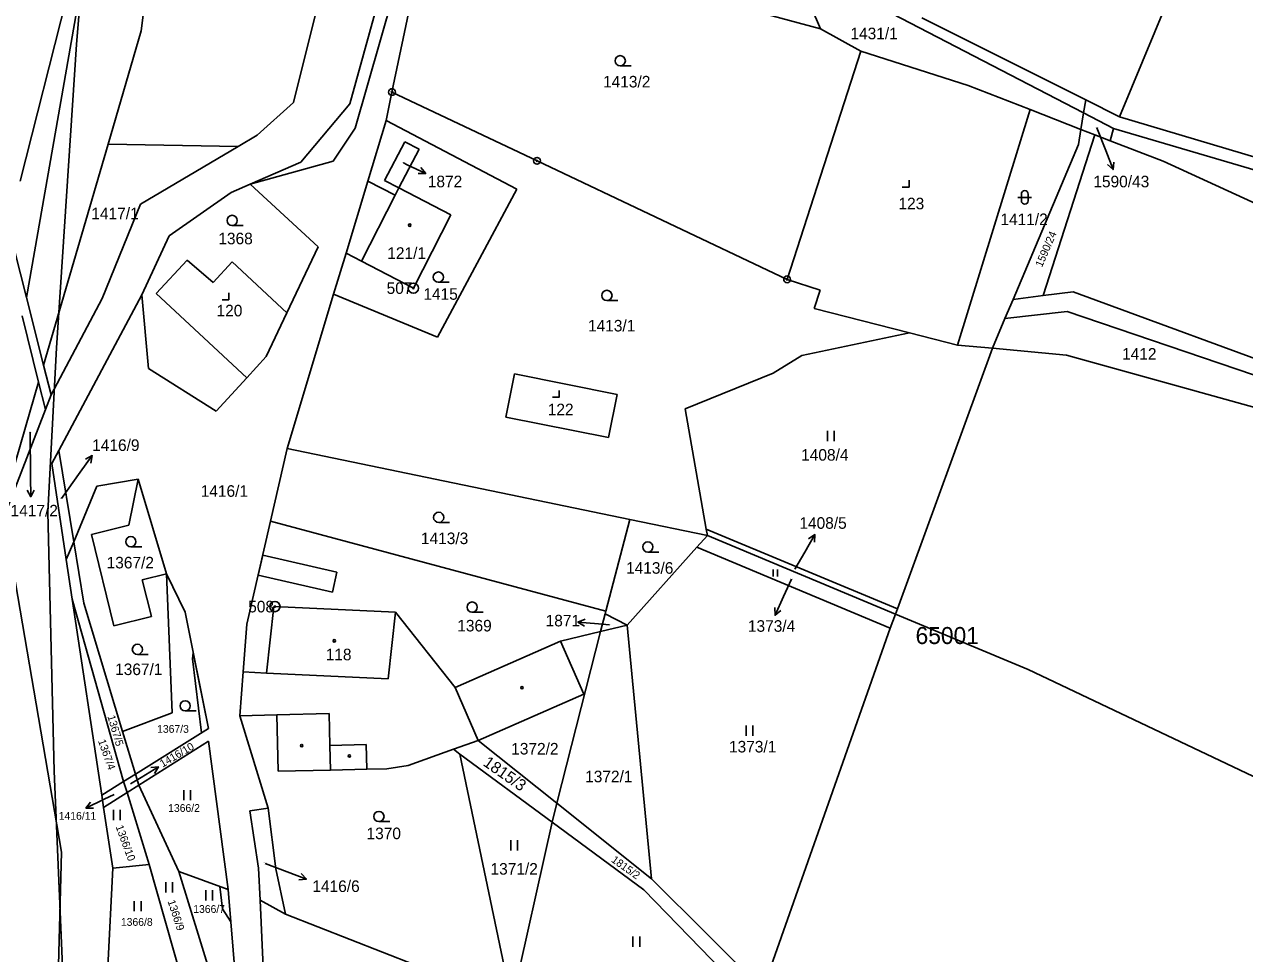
# Model space of a CAD drawing. Extents: x -546762 to -540209, y -1046851 to -1035694.
# Drawn here: x -543585.9 to -543406.7, y -1041154.9 to -1041018.4 of the extents above; entities that cross this region are included whole.
import ezdxf

# ---------------------------------------------------------------- set-up
doc = ezdxf.new("R2010")
doc.units = 0
for name, color, linetype in [('Vrstva 1', 7, 'Continuous'), ('Vrstva 16', 7, 'Continuous'), ('Vrstva 17', 7, 'Continuous'), ('Vrstva 18', 7, 'Continuous'), ('Vrstva 19', 7, 'Continuous'), ('Vrstva 24', 7, 'Continuous'), ('Vrstva 25', 7, 'Continuous'), ('Vrstva 3', 7, 'Continuous'), ('Vrstva 30', 7, 'Continuous'), ('Vrstva 37', 7, 'Continuous'), ('Vrstva 4', 7, 'Continuous'), ('Vrstva 52', 7, 'Continuous'), ('Vrstva 53', 7, 'Continuous'), ('Vrstva 6', 7, 'Continuous')]:
    doc.layers.add(name, color=color, linetype=linetype)

msp = doc.modelspace()

# ---------------------------------------------------------------- linework, layer by layer
at = {"layer": 'Vrstva 1'}
for p, q in [((-543564.16, -1040935.84), (-543585.58, -1041058.49)), ((-543540.21, -1041005.09), (-543546.36, -1041029.86)), ((-543531.75, -1041014.27), (-543537.3, -1041033.62)), ((-543537.3, -1041033.62), (-543540.52, -1041038.48)), ((-543540.52, -1041038.48), (-543552.73, -1041041.85))]:
    msp.add_line(p, q, dxfattribs=at)
for points in [[(-543564.64, -1040987.05), (-543568.73, -1041019.34)], [(-543531.89, -1041028.33), (-543526.68, -1041003.47)], [(-543526.68, -1041003.47), (-543468.97, -1041019.03)], [(-543538.08, -1041030.04), (-543531.44, -1041005.97)], [(-543468.97, -1041019.03), (-543473.2, -1041009.11)], [(-543473.2, -1041009.11), (-543430.31, -1041031.4)], [(-543579.71, -1041014.54), (-543586.53, -1041041.43)], [(-543454.04, -1041017.4), (-543429.99, -1041029.48)], [(-543573.59, -1041036), (-543568.73, -1041019.34)], [(-543468.97, -1041019.03), (-543463.04, -1041022.33)], [(-543463.04, -1041022.33), (-543473.85, -1041055.84)], [(-543463.04, -1041022.33), (-543447.28, -1041027.35)], [(-543447.28, -1041027.35), (-543438.15, -1041030.91)], [(-543531.89, -1041028.33), (-543532.76, -1041032.5)], [(-543510.59, -1041038.43), (-543531.89, -1041028.33)], [(-543551.68, -1041034.65), (-543546.36, -1041029.86)], [(-543538.08, -1041030.04), (-543545.26, -1041038.61)], [(-543438.15, -1041030.91), (-543448.82, -1041065.5)], [(-543438.15, -1041030.91), (-543430.7, -1041033.81)], [(-543430.31, -1041031.4), (-543429.99, -1041029.48)], [(-543532.76, -1041032.5), (-543535.45, -1041041.41)], [(-543532.76, -1041032.5), (-543513.53, -1041042.59)], [(-543430.7, -1041033.81), (-543430.31, -1041031.4)], [(-543551.68, -1041034.65), (-543554.51, -1041036.33)], [(-543431.06, -1041036.04), (-543430.7, -1041033.81)], [(-543583.06, -1041068.45), (-543573.59, -1041036)], [(-543573.59, -1041036), (-543554.51, -1041036.33)], [(-543568.85, -1041044.82), (-543554.51, -1041036.33)], [(-543532.97, -1041041.3), (-543530.02, -1041035.62)], [(-543530.02, -1041035.62), (-543527.92, -1041036.72)], [(-543431.06, -1041036.04), (-543440.65, -1041058.78)], [(-543527.92, -1041036.72), (-543530.87, -1041042.39)], [(-543545.26, -1041038.61), (-543552.73, -1041041.85)], [(-543473.85, -1041055.84), (-543510.59, -1041038.43)], [(-543552.73, -1041041.85), (-543555.51, -1041043.06)], [(-543542.75, -1041051.04), (-543552.73, -1041041.85)], [(-543535.45, -1041041.41), (-543538.64, -1041051.98)], [(-543531.43, -1041043.49), (-543535.45, -1041041.41)], [(-543530.87, -1041042.39), (-543532.97, -1041041.3)], [(-543555.51, -1041043.06), (-543564.64, -1041049.44)], [(-543531.43, -1041043.49), (-543530.87, -1041042.39)], [(-543530.87, -1041042.39), (-543523.24, -1041046.36)], [(-543513.53, -1041042.59), (-543525.21, -1041064.33)], [(-543574.46, -1041058.66), (-543568.85, -1041044.82)], [(-543523.24, -1041046.36), (-543528.75, -1041057.13)], [(-543588.22, -1041048.06), (-543585.58, -1041058.49)], [(-543564.64, -1041049.44), (-543568.66, -1041058.14)], [(-543542.75, -1041051.04), (-543547.34, -1041060.78)], [(-543538.64, -1041051.98), (-543540.46, -1041058.03)], [(-543536.38, -1041053.16), (-543538.64, -1041051.98)], [(-543561.96, -1041053), (-543566.53, -1041057.9)], [(-543558.18, -1041056.28), (-543561.96, -1041053)], [(-543555.39, -1041053.28), (-543558.18, -1041056.28)], [(-543555.39, -1041053.28), (-543547.34, -1041060.78)], [(-543528.75, -1041057.13), (-543536.38, -1041053.16)], [(-543469, -1041057.41), (-543473.85, -1041055.84)], [(-543566.53, -1041057.9), (-543553.23, -1041070.32)], [(-543540.46, -1041058.03), (-543547.28, -1041080.67)], [(-543540.46, -1041058.03), (-543525.21, -1041064.33)], [(-543469, -1041057.41), (-543469.87, -1041060.12)], [(-543585.58, -1041058.49), (-543583.06, -1041068.45)], [(-543581.96, -1041072.79), (-543574.46, -1041058.66)], [(-543568.66, -1041058.14), (-543580.83, -1041080.99)], [(-543567.67, -1041068.94), (-543568.66, -1041058.14)], [(-543440.65, -1041058.78), (-543441.85, -1041061.61)], [(-543586.19, -1041061.19), (-543583.79, -1041070.95)], [(-543547.34, -1041060.78), (-543550.36, -1041067.18)], [(-543469.87, -1041060.12), (-543455.88, -1041063.7)], [(-543441.85, -1041061.61), (-543443.69, -1041065.97)], [(-543471.67, -1041067.04), (-543455.88, -1041063.7)], [(-543455.88, -1041063.7), (-543448.82, -1041065.5)], [(-543471.67, -1041067.04), (-543475.88, -1041069.64)], [(-543443.69, -1041065.97), (-543457.66, -1041104.26)], [(-543448.82, -1041065.5), (-543443.69, -1041065.97)], [(-543583.06, -1041068.45), (-543581.96, -1041072.79)], [(-543550.36, -1041067.18), (-543553.23, -1041070.32)], [(-543567.67, -1041068.94), (-543557.71, -1041075.23)], [(-543553.23, -1041070.32), (-543557.71, -1041075.23)], [(-543513.9, -1041069.73), (-543515.16, -1041076.07)], [(-543498.83, -1041072.74), (-543513.9, -1041069.73)], [(-543475.88, -1041069.64), (-543488.85, -1041074.86)], [(-543591.7, -1041098.06), (-543583.79, -1041070.95)], [(-543583.79, -1041070.95), (-543582.8, -1041074.97)], [(-543582.8, -1041074.97), (-543581.96, -1041072.79)], [(-543498.83, -1041072.74), (-543500.1, -1041079.08)], [(-543588.85, -1041090.66), (-543582.8, -1041074.97)], [(-543485.72, -1041092.52), (-543488.85, -1041074.86)], [(-543515.16, -1041076.07), (-543500.1, -1041079.08)], [(-543580.83, -1041080.99), (-543581.85, -1041082.9)], [(-543580.83, -1041080.99), (-543578.63, -1041094.38)], [(-543547.28, -1041080.67), (-543549.73, -1041091.38)], [(-543581.85, -1041082.9), (-543579.73, -1041097.02)], [(-543578.63, -1041094.38), (-543575.23, -1041086.21)], [(-543575.23, -1041086.21), (-543569.19, -1041085.19)], [(-543569.19, -1041085.19), (-543564.99, -1041099.1)], [(-543580.46, -1041140), (-543588.85, -1041090.66)], [(-543549.73, -1041091.38), (-543553.19, -1041106.51)], [(-543500.5, -1041104.61), (-543549.73, -1041091.38)], [(-543500.5, -1041104.61), (-543496.94, -1041091.1)], [(-543485.55, -1041093.46), (-543487.11, -1041095.2)], [(-543485.55, -1041093.46), (-543485.72, -1041092.52)], [(-543485.72, -1041092.52), (-543457.66, -1041104.26)], [(-543457.94, -1041105.02), (-543485.55, -1041093.46)], [(-543579.73, -1041097.02), (-543578.63, -1041094.38)], [(-543487.11, -1041095.2), (-543497.33, -1041106.65)], [(-543458.7, -1041107.1), (-543487.11, -1041095.2)], [(-543579.73, -1041097.02), (-543578.86, -1041102.82)], [(-543562.29, -1041104.74), (-543564.99, -1041099.1)], [(-543578.86, -1041102.82), (-543574.53, -1041131.64)], [(-543549.25, -1041103.92), (-543550.34, -1041113.68)], [(-543549.25, -1041103.92), (-543531.37, -1041104.75)], [(-543500.59, -1041104.96), (-543500.5, -1041104.61)], [(-543457.66, -1041104.26), (-543457.94, -1041105.02)], [(-543562.29, -1041104.74), (-543558.83, -1041121.81)], [(-543531.37, -1041104.75), (-543522.62, -1041115.8)], [(-543501.26, -1041107.6), (-543500.59, -1041104.96)], [(-543500.59, -1041104.96), (-543497.33, -1041106.65)], [(-543457.94, -1041105.02), (-543458.7, -1041107.1)], [(-543553.19, -1041106.51), (-543553.74, -1041113.52)], [(-543507.67, -1041132.79), (-543501.26, -1041107.6)], [(-543501.26, -1041107.6), (-543507.14, -1041109.01)], [(-543497.33, -1041106.65), (-543501.26, -1041107.6)], [(-543497.33, -1041106.65), (-543493.75, -1041143.91)], [(-543477.44, -1041160.15), (-543458.7, -1041107.1)], [(-543507.14, -1041109.01), (-543522.62, -1041115.8)], [(-543507.14, -1041109.01), (-543503.73, -1041116.78)], [(-543553.74, -1041113.52), (-543554.23, -1041119.95)], [(-543553.74, -1041113.52), (-543550.34, -1041113.68)], [(-543503.73, -1041116.78), (-543519.21, -1041123.57)], [(-543554.23, -1041119.95), (-543548.82, -1041119.82)], [(-543554.23, -1041119.95), (-543550.09, -1041133.54)], [(-543548.82, -1041119.82), (-543548.63, -1041128.12)], [(-543558.83, -1041121.81), (-543569.59, -1041128.54)], [(-543558.82, -1041123.68), (-543569.1, -1041130.17)], [(-543558.82, -1041123.68), (-543555.97, -1041145.47)], [(-543522.86, -1041124.88), (-543519.21, -1041123.57)], [(-543519.21, -1041123.57), (-543507.67, -1041132.79)], [(-543529.53, -1041127.26), (-543522.86, -1041124.88)], [(-543521.91, -1041125.58), (-543522.86, -1041124.88)], [(-543508.38, -1041135.57), (-543521.91, -1041125.58)], [(-543514.28, -1041162.12), (-543521.91, -1041125.58)], [(-543548.63, -1041128.12), (-543540.93, -1041127.94)], [(-543540.93, -1041127.94), (-543535.58, -1041127.82)], [(-543535.58, -1041127.82), (-543532.65, -1041127.75)], [(-543532.65, -1041127.75), (-543529.53, -1041127.26)], [(-543571.31, -1041129.62), (-543574.53, -1041131.64)], [(-543569.59, -1041128.54), (-543571.31, -1041129.62)], [(-543571.31, -1041129.62), (-543570.81, -1041131.25)], [(-543569.59, -1041128.54), (-543569.1, -1041130.17)], [(-543570.81, -1041131.25), (-543574.26, -1041133.43)], [(-543569.1, -1041130.17), (-543570.81, -1041131.25)], [(-543574.53, -1041131.64), (-543574.26, -1041133.43)], [(-543508.38, -1041135.57), (-543507.67, -1041132.79)], [(-543507.67, -1041132.79), (-543493.75, -1041143.91)], [(-543574.26, -1041133.43), (-543572.92, -1041142.34)], [(-543552.76, -1041133.91), (-543550.09, -1041133.54)], [(-543552.76, -1041133.91), (-543551.48, -1041142.37)], [(-543550.09, -1041133.54), (-543548.96, -1041142.45)], [(-543514.28, -1041162.12), (-543508.38, -1041135.57)], [(-543494.88, -1041145.53), (-543508.38, -1041135.57)], [(-543580.46, -1041140), (-543581.72, -1041187.92)], [(-543572.92, -1041142.34), (-543573.64, -1041156.84)], [(-543551.48, -1041142.37), (-543551.27, -1041147.03)], [(-543548.96, -1041142.45), (-543547.55, -1041149.13)], [(-543493.75, -1041143.91), (-543477.44, -1041160.15)], [(-543555.97, -1041145.47), (-543554.51, -1041163.33)], [(-543494.88, -1041145.53), (-543478.32, -1041162.62)], [(-543551.27, -1041147.03), (-543549.65, -1041183.25)], [(-543551.27, -1041147.03), (-543547.55, -1041149.13)], [(-543547.55, -1041149.13), (-543514.28, -1041162.12)]]:
    msp.add_lwpolyline(points, dxfattribs=at)
at = {"layer": 'Vrstva 16'}
for p, q in [((-543427.05, -1041036.93), (-543425.96, -1041039.72)), ((-543529.65, -1041039), (-543526.94, -1041040.28)), ((-543577.68, -1041084.18), (-543575.93, -1041081.74)), ((-543584.98, -1041084.79), (-543584.95, -1041087.79)), ((-543471.27, -1041095.93), (-543469.77, -1041093.33)), ((-543474.37, -1041102.45), (-543475.62, -1041105.18)), ((-543501.58, -1041106.44), (-543504.57, -1041106.2)), ((-543568.75, -1041129.03), (-543566.19, -1041127.47)), ((-543574.15, -1041132.23), (-543576.85, -1041133.53)), ((-543547.27, -1041142.88), (-543544.46, -1041143.94))]:
    msp.add_line(p, q, dxfattribs=at)
for points in [[(-543428.36, -1041033.58), (-543427.05, -1041036.93)], [(-543530.21, -1041038.74), (-543529.65, -1041039)], [(-543527.63, -1041039.4), (-543526.94, -1041040.28), (-543528.06, -1041040.31)], [(-543425.86, -1041038.61), (-543425.96, -1041039.72), (-543426.79, -1041038.97)], [(-543585.04, -1041078.3), (-543584.98, -1041084.79)], [(-543576.92, -1041082.26), (-543575.93, -1041081.74), (-543576.11, -1041082.85)], [(-543580.46, -1041088.04), (-543577.68, -1041084.18)], [(-543584.46, -1041086.79), (-543584.95, -1041087.79), (-543585.46, -1041086.79)], [(-543470.7, -1041093.95), (-543469.77, -1041093.33), (-543469.83, -1041094.45)], [(-543472.72, -1041098.42), (-543471.27, -1041095.93)], [(-543473.19, -1041099.9), (-543474.37, -1041102.45)], [(-543474.75, -1041104.48), (-543475.62, -1041105.18), (-543475.66, -1041104.06)], [(-543503.61, -1041106.78), (-543504.57, -1041106.2), (-543503.53, -1041105.78)], [(-543499.94, -1041106.58), (-543501.58, -1041106.44)], [(-543567.3, -1041127.56), (-543566.19, -1041127.47), (-543566.78, -1041128.42)], [(-543570.3, -1041129.97), (-543568.75, -1041129.03)], [(-543572.71, -1041131.54), (-543574.15, -1041132.23)], [(-543575.74, -1041133.55), (-543576.85, -1041133.53), (-543576.17, -1041132.65)], [(-543550.54, -1041141.65), (-543547.27, -1041142.88)], [(-543545.22, -1041143.12), (-543544.46, -1041143.94), (-543545.58, -1041144.05)]]:
    msp.add_lwpolyline(points, dxfattribs=at)
at = {"layer": 'Vrstva 24'}
for centre, radius in [((-543531.89, -1041028.33), 0.5), ((-543531.89, -1041028.33), 0.1), ((-543510.59, -1041038.43), 0.5), ((-543510.59, -1041038.43), 0.1), ((-543473.85, -1041055.84), 0.5), ((-543473.85, -1041055.84), 0.1), ((-543528.75, -1041057.13), 0.75), ((-543528.75, -1041057.13), 0.1), ((-543549.09, -1041103.92), 0.75), ((-543549.09, -1041103.92), 0.1)]:
    msp.add_circle(centre, radius, dxfattribs=at)
at = {"layer": 'Vrstva 25'}
for p, q in [((-543498.36, -1041024.47), (-543496.76, -1041024.47)), ((-543439.44, -1041044.31), (-543439.44, -1041043.31)), ((-543438.44, -1041043.31), (-543438.44, -1041044.31)), ((-543439.94, -1041043.81), (-543437.94, -1041043.81)), ((-543555.37, -1041047.93), (-543553.77, -1041047.93)), ((-543525.08, -1041056.26), (-543523.48, -1041056.26)), ((-543500.32, -1041058.95), (-543498.72, -1041058.95)), ((-543467.92, -1041079.6), (-543467.92, -1041078.1)), ((-543466.92, -1041079.6), (-543466.92, -1041078.1)), ((-543525.03, -1041091.56), (-543523.43, -1041091.56)), ((-543570.25, -1041095.13), (-543568.65, -1041095.13)), ((-543494.31, -1041095.91), (-543492.71, -1041095.91)), ((-543475.92, -1041099.48), (-543475.92, -1041098.47)), ((-543475.24, -1041099.48), (-543475.24, -1041098.47)), ((-543520.12, -1041104.74), (-543518.52, -1041104.74)), ((-543569.29, -1041110.95), (-543567.69, -1041110.95)), ((-543562.27, -1041119.24), (-543560.67, -1041119.24)), ((-543479.88, -1041122.89), (-543479.88, -1041121.39)), ((-543478.88, -1041122.89), (-543478.88, -1041121.39)), ((-543562.47, -1041132.38), (-543562.47, -1041130.88)), ((-543561.47, -1041132.38), (-543561.47, -1041130.88)), ((-543572.82, -1041135.3), (-543572.82, -1041133.8)), ((-543571.82, -1041135.3), (-543571.82, -1041133.8)), ((-543533.81, -1041135.51), (-543532.21, -1041135.51)), ((-543514.45, -1041139.73), (-543514.45, -1041138.23)), ((-543513.45, -1041139.73), (-543513.45, -1041138.23)), ((-543565.13, -1041145.9), (-543565.13, -1041144.4)), ((-543564.13, -1041145.9), (-543564.13, -1041144.4)), ((-543559.24, -1041147.08), (-543559.24, -1041145.58)), ((-543558.24, -1041147.08), (-543558.24, -1041145.58)), ((-543569.75, -1041148.68), (-543569.75, -1041147.18)), ((-543568.75, -1041148.68), (-543568.75, -1041147.18)), ((-543496.5, -1041153.9), (-543496.5, -1041152.4)), ((-543495.5, -1041153.9), (-543495.5, -1041152.4))]:
    msp.add_line(p, q, dxfattribs=at)
for points in [[(-543456.94, -1041042.29), (-543455.94, -1041042.29), (-543455.94, -1041041.29)], [(-543556.86, -1041058.83), (-543555.86, -1041058.83), (-543555.86, -1041057.83)], [(-543508.33, -1041073.15), (-543507.33, -1041073.15), (-543507.33, -1041072.15)]]:
    msp.add_lwpolyline(points, dxfattribs=at)
for centre, radius in [((-543498.36, -1041023.72), 0.75), ((-543555.37, -1041047.18), 0.75), ((-543529.28, -1041047.88), 0.175), ((-543525.08, -1041055.51), 0.75), ((-543500.32, -1041058.2), 0.75), ((-543525.03, -1041090.81), 0.75), ((-543570.25, -1041094.38), 0.75), ((-543494.31, -1041095.16), 0.75), ((-543520.12, -1041103.99), 0.75), ((-543569.29, -1041110.2), 0.75), ((-543540.38, -1041108.95), 0.175), ((-543512.8, -1041115.84), 0.175), ((-543562.27, -1041118.49), 0.75), ((-543545.15, -1041124.35), 0.175), ((-543538.15, -1041125.86), 0.175), ((-543533.81, -1041134.76), 0.75)]:
    msp.add_circle(centre, radius, dxfattribs=at)
for centre, start, end in [((-543438.94, -1041043.31), 0, 180), ((-543438.94, -1041044.31), 180, 0)]:
    msp.add_arc(centre, 0.5, start, end, dxfattribs=at)
at = {"layer": 'Vrstva 3'}
for points in [[(-543579.71, -1041014.54), (-543586.53, -1041041.43)], [(-543531.43, -1041043.49), (-543536.38, -1041053.16)], [(-543531.43, -1041043.49), (-543530.87, -1041042.39)], [(-543530.87, -1041042.39), (-543523.24, -1041046.36)], [(-543523.24, -1041046.36), (-543528.75, -1041057.13)], [(-543528.75, -1041057.13), (-543536.38, -1041053.16)], [(-543549.25, -1041103.92), (-543550.34, -1041113.68)], [(-543549.25, -1041103.92), (-543531.37, -1041104.75)], [(-543531.37, -1041104.75), (-543532.46, -1041114.51)], [(-543532.46, -1041114.51), (-543550.34, -1041113.68)]]:
    msp.add_lwpolyline(points, dxfattribs=at)
at = {"layer": 'Vrstva 30'}
for points in [[(-543539.97, -1041098.86), (-543540.63, -1041101.78), (-543551.54, -1041099.3), (-543550.87, -1041096.38), (-543539.97, -1041098.86)], [(-543561.17, -1041111.57), (-543561.08, -1041110.72), (-543558.83, -1041121.81), (-543559.87, -1041122.46), (-543561.17, -1041111.57)], [(-543556.79, -1041148.31), (-543557.18, -1041145.03), (-543555.97, -1041145.47), (-543555.58, -1041150.24), (-543556.79, -1041148.31)]]:
    msp.add_lwpolyline(points, dxfattribs=at)
at = {"layer": 'Vrstva 37'}
for centre in [(-543529.28, -1041047.88), (-543540.38, -1041108.95)]:
    msp.add_circle(centre, 0.175, dxfattribs=at)
at = {"layer": 'Vrstva 4'}
for points in [[(-543531.43, -1041043.49), (-543536.38, -1041053.16)], [(-543531.37, -1041104.75), (-543532.46, -1041114.51)], [(-543532.46, -1041114.51), (-543550.34, -1041113.68)], [(-543519.21, -1041123.57), (-543522.62, -1041115.8)], [(-543541.12, -1041119.64), (-543548.82, -1041119.82)], [(-543541.12, -1041119.64), (-543541.01, -1041124.31)], [(-543541.01, -1041124.31), (-543535.66, -1041124.19)], [(-543541.01, -1041124.31), (-543540.93, -1041127.94)], [(-543535.66, -1041124.19), (-543535.58, -1041127.82)]]:
    msp.add_lwpolyline(points, dxfattribs=at)
at = {"layer": 'Vrstva 52'}
msp.add_lwpolyline([(-543575.66, -1040989.97), (-543578.21, -1041021.36), (-543581.17, -1041065.89), (-543582.45, -1041090.06), (-543581.53, -1041128.11), (-543578.94, -1041188.97), (-543579.68, -1041229.79), (-543580.05, -1041272.47), (-543581.53, -1041313.66)], dxfattribs=at)
at = {"layer": 'Vrstva 6'}
for points in [[(-543413.07, -1041003.19), (-543425.02, -1041031.98)], [(-543425.02, -1041031.98), (-543429.99, -1041029.48)], [(-543430.31, -1041031.4), (-543425.91, -1041033.68)], [(-543425.02, -1041031.98), (-543388.72, -1041042.77)], [(-543428.67, -1041034.6), (-543436.23, -1041058.23)], [(-543428.67, -1041034.6), (-543430.7, -1041033.81)], [(-543426.38, -1041035.49), (-543428.67, -1041034.6)], [(-543425.91, -1041033.68), (-543426.38, -1041035.49)], [(-543425.91, -1041033.68), (-543388.46, -1041044.69)], [(-543418.63, -1041038.5), (-543426.38, -1041035.49)], [(-543390.74, -1041051.26), (-543418.63, -1041038.5)], [(-543436.23, -1041058.23), (-543431.81, -1041057.67)], [(-543431.81, -1041057.67), (-543396.93, -1041070.5)], [(-543440.65, -1041058.78), (-543436.23, -1041058.23)], [(-543441.85, -1041061.61), (-543432.7, -1041060.57)], [(-543432.7, -1041060.57), (-543395.4, -1041073.26)], [(-543432.81, -1041066.97), (-543443.69, -1041065.97)], [(-543432.81, -1041066.97), (-543394.55, -1041077.61)], [(-543496.94, -1041091.1), (-543547.28, -1041080.67)], [(-543569.19, -1041085.19), (-543570.56, -1041091.98)], [(-543570.56, -1041091.98), (-543576.05, -1041093.34)], [(-543485.55, -1041093.46), (-543496.94, -1041091.1)], [(-543576.05, -1041093.34), (-543572.73, -1041106.74)], [(-543578.63, -1041094.38), (-543577.15, -1041103.4)], [(-543564.99, -1041099.1), (-543568.58, -1041099.99)], [(-543564.17, -1041119.53), (-543564.99, -1041099.1)], [(-543568.58, -1041099.99), (-543567.24, -1041105.38)], [(-543571.31, -1041129.62), (-543578.86, -1041102.82)], [(-543577.15, -1041103.4), (-543571.48, -1041122.25)], [(-543572.73, -1041106.74), (-543567.24, -1041105.38)], [(-543438.46, -1041113.18), (-543457.94, -1041105.02)], [(-543438.46, -1041113.18), (-543368.51, -1041146.37)], [(-543571.48, -1041122.25), (-543564.17, -1041119.53)], [(-543571.48, -1041122.25), (-543569.59, -1041128.54)], [(-543567.58, -1041141.79), (-543570.81, -1041131.25)], [(-543569.1, -1041130.17), (-543563.18, -1041142.84)], [(-543572.92, -1041142.34), (-543567.58, -1041141.79)], [(-543567.58, -1041141.79), (-543562.78, -1041158.69)], [(-543555.97, -1041145.47), (-543563.18, -1041142.84)], [(-543563.18, -1041142.84), (-543556.72, -1041163.81)]]:
    msp.add_lwpolyline(points, dxfattribs=at)

# ---------------------------------------------------------------- texts
at = {"layer": 'Vrstva 16'}
for s, height, p in [('1872', 1.7, (-543526.63, -1041042.31)), ('1590/43', 1.7, (-543428.87, -1041042.32)), ('1416/9', 1.7, (-543575.93, -1041081.05)), ('1417/2', 1.7, (-543587.92, -1041090.67)), ('1408/5', 1.7, (-543472.05, -1041092.49)), ('1871', 1.7, (-543509.32, -1041106.83)), ('1373/4', 1.7, (-543479.61, -1041107.62)), ('1416/11', 1.14, (-543580.84, -1041135.23)), ('1416/6', 1.7, (-543543.59, -1041145.85))]:
    msp.add_text(s, height=height, dxfattribs=at).set_placement(p)
msp.add_text('1416/10', height=1.14, rotation=30.6084, dxfattribs=at).set_placement((-543565.58, -1041127.59))
at = {"layer": 'Vrstva 17'}
for s, p in [('507', (-543532.68, -1041057.98)), ('508', (-543553.01, -1041104.77))]:
    msp.add_text(s, height=1.7, dxfattribs=at).set_placement(p)
at = {"layer": 'Vrstva 18'}
for s, height, p in [('1431/1', 1.7, (-543464.55, -1041020.57)), ('1413/2', 1.7, (-543500.89, -1041027.65)), ('1590/43', 0.1, (-543428.61, -1041033.58)), ('1872', 0.1, (-543530.34, -1041038.74)), ('1417/1', 1.7, (-543576.06, -1041047.02)), ('1411/2', 1.7, (-543442.52, -1041047.87)), ('1368', 1.7, (-543557.4, -1041050.69)), ('1415', 1.7, (-543527.28, -1041058.84)), ('1413/1', 1.7, (-543503.1, -1041063.5)), ('1412', 1.7, (-543424.65, -1041067.64)), ('1417/2', 0.1, (-543585.23, -1041078.3)), ('1408/4', 1.7, (-543471.79, -1041082.48)), ('1416/1', 1.7, (-543559.99, -1041087.79)), ('1416/9', 0.1, (-543580.66, -1041088.04)), ('1413/3', 1.7, (-543527.64, -1041094.74)), ('1367/2', 1.7, (-543573.81, -1041098.31)), ('1413/6', 1.7, (-543497.51, -1041099.09)), ('1408/5', 0.1, (-543472.93, -1041098.42)), ('1373/4', 0.1, (-543473.4, -1041099.9)), ('1369', 1.7, (-543522.3, -1041107.57)), ('1871', 0.1, (-543500.05, -1041106.58)), ('1367/1', 1.7, (-543572.56, -1041113.98)), ('1367/3', 1.14, (-543566.39, -1041122.46)), ('1372/2', 1.7, (-543514.38, -1041125.65)), ('1373/1', 1.7, (-543482.39, -1041125.35)), ('1372/1', 1.7, (-543503.52, -1041129.73)), ('1416/11', 0.1, (-543572.91, -1041131.54)), ('1416/10', 0.1, (-543570.52, -1041129.97)), ('1366/2', 1.14, (-543564.77, -1041134.08)), ('1370', 1.7, (-543535.63, -1041138.09)), ('1416/6', 0.1, (-543550.74, -1041141.65)), ('1371/2', 1.7, (-543517.42, -1041143.3)), ('1366/7', 1.14, (-543561.08, -1041148.92)), ('1366/8', 1.14, (-543571.71, -1041150.82))]:
    msp.add_text(s, height=height, dxfattribs=at).set_placement(p)
for s, height, rotation, p in [('1590/24', 1.14, 66.6513, (-543436.41, -1041054.14)), ('1367/5', 1.14, 286.3672, (-543573.7, -1041120.05)), ('1367/4', 1.14, 289.391, (-543575.09, -1041123.64)), ('1815/3', 1.7, 325.1649, (-543518.64, -1041127.17)), ('1366/10', 1.14, 290.1307, (-543572.5, -1041136.25)), ('1815/2', 1.14, 324.5087, (-543499.77, -1041141.34)), ('1366/9', 1.14, 288.1405, (-543564.87, -1041147.21))]:
    msp.add_text(s, height=height, rotation=rotation, dxfattribs=at).set_placement(p)
at = {"layer": 'Vrstva 19'}
for s, p in [('123', (-543457.5, -1041045.55)), ('121/1', (-543532.58, -1041052.83)), ('120', (-543557.66, -1041061.28)), ('122', (-543509.01, -1041075.81)), ('118', (-543541.63, -1041111.81))]:
    msp.add_text(s, height=1.7, dxfattribs=at).set_placement(p)
at = {"layer": 'Vrstva 53'}
msp.add_text('65001', height=2.5, dxfattribs=at).set_placement((-543454.98, -1041109.42))

doc.saveas('drawing.dxf')
